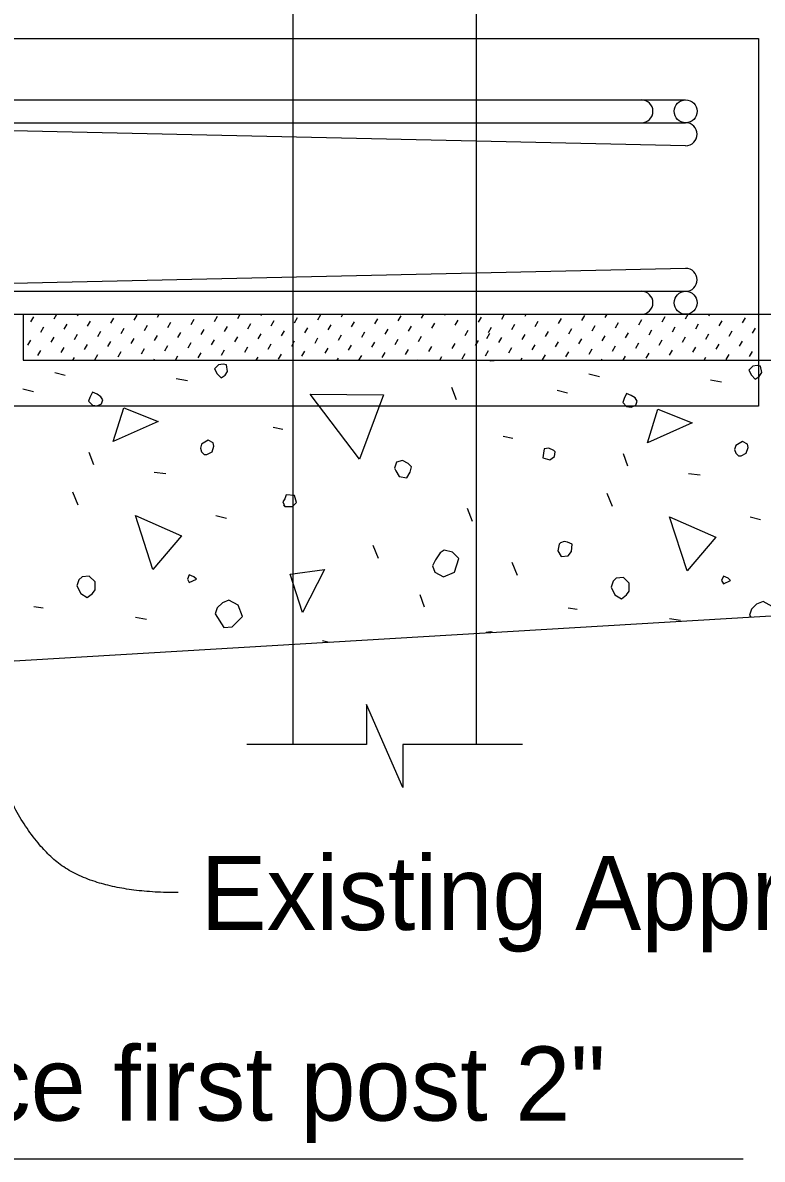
# Model space of a CAD drawing. Extents: x 1 to 39.2, y 0 to 26.
# Drawn here: x 7.686 to 9.698, y 8.522 to 11.612 of the extents above; entities that cross this region are included whole.
import ezdxf

# ---------------------------------------------------------------- set-up
doc = ezdxf.new("R2010")
doc.units = 0
for name, color, linetype in [('Dimension', 7, 'Continuous'), ('Miscellaneous', 7, 'Continuous'), ('Rebar', 7, 'Continuous'), ('TextStructures', 7, 'Continuous'), ('TrafBarrierConc', 7, 'Continuous')]:
    doc.layers.add(name, color=color, linetype=linetype)

msp = doc.modelspace()

# ---------------------------------------------------------------- linework, layer by layer
at = {"layer": 'Dimension'}
msp.add_line((9.6459, 8.5219), (6.3055, 8.5219), dxfattribs=at)
msp.add_lwpolyline([(9.0455, 9.6494), (8.7202, 9.6494), (8.7202, 9.5332), (8.6208, 9.7582), (8.6208, 9.6494), (8.2955, 9.6494)], dxfattribs=at)
msp.add_open_spline([(8.1083, 9.2469), (7.8622, 9.2469), (7.6571, 9.4476), (7.5614, 9.7898), (7.5876, 10.3007)], degree=2, dxfattribs=at)
at = {"layer": 'Miscellaneous'}
for p, q in [((7.771, 10.8069), (7.7784, 10.8196)), ((7.8345, 10.815), (7.8372, 10.8196)), ((7.9892, 10.8035), (7.9973, 10.8175)), ((8.0527, 10.8116), (8.0573, 10.8196)), ((8.2708, 10.8082), (8.2775, 10.8196)), ((8.3343, 10.8163), (8.3363, 10.8196)), ((8.489, 10.8048), (8.4971, 10.8188)), ((8.5525, 10.8129), (8.5564, 10.8196)), ((8.7707, 10.8095), (8.7765, 10.8196)), ((8.8342, 10.8176), (8.8353, 10.8196)), ((8.9888, 10.8061), (8.9967, 10.8196)), ((9.0523, 10.8142), (9.0555, 10.8196)), ((9.2705, 10.8108), (9.2756, 10.8196)), ((9.334, 10.8189), (9.3344, 10.8196)), ((9.4887, 10.8075), (9.4957, 10.8196)), ((9.5522, 10.8156), (9.5545, 10.8196)), ((7.7075, 10.7988), (7.7156, 10.8128)), ((7.7987, 10.7792), (7.8068, 10.7932)), ((7.8622, 10.7873), (7.8703, 10.8013)), ((7.9257, 10.7954), (7.9338, 10.8094)), ((8.0169, 10.7758), (8.025, 10.7898)), ((8.0804, 10.7839), (8.0885, 10.7979)), ((8.1438, 10.792), (8.1519, 10.806)), ((8.2073, 10.8001), (8.2154, 10.8141)), ((8.235, 10.7724), (8.2431, 10.7864)), ((8.2985, 10.7805), (8.3066, 10.7945)), ((8.362, 10.7886), (8.3701, 10.8026)), ((8.4255, 10.7967), (8.4336, 10.8107)), ((8.5167, 10.7771), (8.5248, 10.7911)), ((8.5802, 10.7852), (8.5883, 10.7992)), ((8.6437, 10.7933), (8.6518, 10.8073)), ((8.7072, 10.8014), (8.7153, 10.8154)), ((8.7349, 10.7737), (8.743, 10.7877)), ((8.7984, 10.7818), (8.8065, 10.7958)), ((8.8619, 10.7899), (8.87, 10.8039)), ((8.9253, 10.798), (8.9334, 10.812)), ((9.0165, 10.7784), (9.0246, 10.7924)), ((9.08, 10.7865), (9.0881, 10.8005)), ((9.1435, 10.7946), (9.1516, 10.8086)), ((9.207, 10.8027), (9.2151, 10.8167)), ((9.2347, 10.775), (9.2428, 10.789)), ((9.2982, 10.7832), (9.3063, 10.7971)), ((9.3617, 10.7913), (9.3698, 10.8052)), ((9.4252, 10.7994), (9.4333, 10.8134)), ((9.5164, 10.7798), (9.5245, 10.7938)), ((9.5799, 10.7879), (9.588, 10.8019)), ((9.6434, 10.796), (9.6515, 10.81)), ((7.7352, 10.7711), (7.7433, 10.7851)), ((7.7629, 10.7434), (7.771, 10.7574)), ((7.8264, 10.7515), (7.8345, 10.7655)), ((7.8899, 10.7596), (7.898, 10.7736)), ((7.9534, 10.7677), (7.9615, 10.7817)), ((8.0446, 10.7481), (8.0527, 10.7621)), ((8.108, 10.7562), (8.1161, 10.7702)), ((8.1715, 10.7643), (8.1796, 10.7783)), ((8.2627, 10.7447), (8.2708, 10.7587)), ((8.3262, 10.7528), (8.3343, 10.7668)), ((8.3897, 10.7609), (8.3978, 10.7749)), ((8.4532, 10.769), (8.4613, 10.783)), ((8.4809, 10.7413), (8.489, 10.7553)), ((8.5444, 10.7494), (8.5525, 10.7634)), ((8.6079, 10.7575), (8.616, 10.7715)), ((8.6714, 10.7656), (8.6795, 10.7796)), ((8.7626, 10.746), (8.7707, 10.76)), ((8.8895, 10.7622), (8.8976, 10.7762)), ((8.9485, 10.7541), (8.9566, 10.7681)), ((8.953, 10.7703), (8.9611, 10.7843)), ((8.9807, 10.7426), (8.9888, 10.7566)), ((9.0442, 10.7507), (9.0523, 10.7647)), ((9.1077, 10.7588), (9.1158, 10.7728)), ((9.1712, 10.7669), (9.1793, 10.7809)), ((9.2624, 10.7474), (9.2705, 10.7613)), ((9.3259, 10.7555), (9.334, 10.7695)), ((9.3894, 10.7636), (9.3975, 10.7776)), ((9.4529, 10.7717), (9.461, 10.7857)), ((9.4806, 10.744), (9.4887, 10.758)), ((9.5441, 10.7521), (9.5522, 10.7661)), ((9.6076, 10.7602), (9.6157, 10.7742)), ((9.671, 10.7683), (9.6792, 10.7823)), ((7.6994, 10.7353), (7.7075, 10.7493)), ((7.7906, 10.7157), (7.7987, 10.7297)), ((7.8541, 10.7238), (7.8622, 10.7378)), ((7.9176, 10.7319), (7.9257, 10.7459)), ((7.9811, 10.74), (7.9892, 10.754)), ((8.0088, 10.7123), (8.0169, 10.7263)), ((8.0723, 10.7204), (8.0804, 10.7344)), ((8.1357, 10.7285), (8.1438, 10.7425)), ((8.1992, 10.7366), (8.2073, 10.7506)), ((8.2904, 10.717), (8.2985, 10.731)), ((8.3539, 10.7251), (8.362, 10.7391)), ((8.4174, 10.7332), (8.4255, 10.7472)), ((8.5086, 10.7136), (8.5167, 10.7276)), ((8.5721, 10.7217), (8.5802, 10.7357)), ((8.6356, 10.7298), (8.6437, 10.7438)), ((8.6991, 10.7379), (8.7072, 10.7519)), ((8.7903, 10.7183), (8.7984, 10.7323)), ((8.8538, 10.7264), (8.8619, 10.7404)), ((8.9172, 10.7345), (8.9253, 10.7485)), ((9.0084, 10.7149), (9.0165, 10.7289)), ((9.0719, 10.723), (9.08, 10.737)), ((9.1354, 10.7311), (9.1435, 10.7451)), ((9.1989, 10.7393), (9.207, 10.7532)), ((9.2266, 10.7116), (9.2347, 10.7256)), ((9.2901, 10.7197), (9.2982, 10.7337)), ((9.3536, 10.7278), (9.3617, 10.7418)), ((9.4171, 10.7359), (9.4252, 10.7499)), ((9.5083, 10.7163), (9.5164, 10.7303)), ((9.5718, 10.7244), (9.5799, 10.7384)), ((9.6353, 10.7325), (9.6434, 10.7465)), ((7.7271, 10.7076), (7.7352, 10.7216)), ((7.8221, 10.6946), (7.8264, 10.702)), ((7.8818, 10.6961), (7.8899, 10.7101)), ((7.9453, 10.7042), (7.9534, 10.7182)), ((8.0423, 10.6946), (8.0446, 10.6986)), ((8.1011, 10.6946), (8.108, 10.7067)), ((8.1634, 10.7008), (8.1715, 10.7148)), ((8.2269, 10.7089), (8.235, 10.7229)), ((8.2624, 10.6946), (8.2627, 10.6952)), ((8.3212, 10.6946), (8.3262, 10.7033)), ((8.3816, 10.6974), (8.3897, 10.7114)), ((8.4451, 10.7055), (8.4532, 10.7195)), ((8.5413, 10.6946), (8.5444, 10.6999)), ((8.6001, 10.6946), (8.6079, 10.708)), ((8.6633, 10.7021), (8.6714, 10.7161)), ((8.7268, 10.7102), (8.7349, 10.7242)), ((8.7615, 10.6946), (8.7626, 10.6965)), ((8.8203, 10.6946), (8.8261, 10.7046)), ((8.8814, 10.6987), (8.8895, 10.7127)), ((8.9449, 10.7068), (8.953, 10.7208)), ((9.0404, 10.6946), (9.0442, 10.7012)), ((9.0996, 10.6954), (9.1077, 10.7093)), ((9.1631, 10.7035), (9.1712, 10.7174)), ((9.2605, 10.6946), (9.2624, 10.6979)), ((9.3193, 10.6946), (9.3259, 10.706)), ((9.3813, 10.7001), (9.3894, 10.7141)), ((9.4448, 10.7082), (9.4529, 10.7222)), ((9.5395, 10.6946), (9.5441, 10.7026)), ((9.5995, 10.6967), (9.6076, 10.7107)), ((9.6629, 10.7048), (9.671, 10.7188)), ((7.773, 10.661), (7.8013, 10.6539)), ((8.1036, 10.6451), (8.1336, 10.6398)), ((9.2261, 10.6575), (9.2544, 10.6504)), ((9.5567, 10.6416), (9.5867, 10.6363)), ((7.6864, 10.6168), (7.7147, 10.6097)), ((8.8655, 10.5868), (8.8531, 10.6204)), ((9.1395, 10.6133), (9.1678, 10.6062)), ((8.367, 10.5125), (8.3935, 10.5072)), ((8.9927, 10.4878), (9.0193, 10.4825)), ((7.8791, 10.41), (7.8667, 10.4436)), ((9.3322, 10.4065), (9.3198, 10.44)), ((8.0435, 10.3905), (8.0753, 10.387)), ((9.4966, 10.387), (9.5284, 10.3835)), ((7.8366, 10.3004), (7.8225, 10.3357)), ((9.2897, 10.2969), (9.2756, 10.3322)), ((8.2114, 10.2721), (8.2397, 10.265)), ((8.9097, 10.2562), (8.8955, 10.2915)), ((9.6645, 10.2686), (9.6928, 10.2615)), ((8.6533, 10.1554), (8.6392, 10.1908)), ((9.0316, 10.1095), (9.0175, 10.1448)), ((8.7789, 10.0228), (8.7665, 10.0564)), ((7.7164, 10.0246), (7.7412, 10.0211)), ((9.1695, 10.0211), (9.1943, 10.0175)), ((7.9922, 9.9963), (8.0222, 9.991)), ((9.4453, 9.9928), (9.4754, 9.9875)), ((8.5013, 9.9327), (8.5195, 9.9281))]:
    msp.add_line(p, q, dxfattribs=at)
for points in [[(8.9204, 9.6494), (8.9204, 13.4695), (8.4204, 13.4695), (8.4204, 9.6494)], [(8.9563, 10.6946), (8.9574, 10.6928), (8.9804, 10.6946), (8.9804, 10.6946)], [(8.2149, 10.6575), (8.2255, 10.6469), (8.2361, 10.6539), (8.2432, 10.6645), (8.2397, 10.6822), (8.2308, 10.684), (8.2185, 10.6822), (8.2079, 10.6716), (8.2149, 10.6575)], [(9.668, 10.6539), (9.6786, 10.6433), (9.6892, 10.6504), (9.6963, 10.661), (9.6928, 10.6787), (9.6839, 10.6805), (9.6716, 10.6787), (9.661, 10.6681), (9.668, 10.6539)], [(7.8755, 10.5726), (7.8879, 10.5709), (7.9003, 10.5762), (7.9038, 10.5868), (7.8985, 10.5956), (7.8879, 10.6027), (7.8755, 10.608), (7.8685, 10.5938), (7.8649, 10.5832), (7.8755, 10.5726)], [(8.6021, 10.4259), (8.4677, 10.6027), (8.6675, 10.6009), (8.6021, 10.4259)], [(9.3286, 10.5691), (9.341, 10.5673), (9.3534, 10.5726), (9.3569, 10.5832), (9.3516, 10.5921), (9.341, 10.5991), (9.3286, 10.6044), (9.3216, 10.5903), (9.318, 10.5797), (9.3286, 10.5691)], [(7.9321, 10.4736), (7.9604, 10.5656), (8.0541, 10.5284), (7.9321, 10.4736)], [(9.3852, 10.4701), (9.4135, 10.562), (9.5072, 10.5249), (9.3852, 10.4701)], [(8.1796, 10.4383), (8.1866, 10.4383), (8.2008, 10.4453), (8.2061, 10.4613), (8.2043, 10.4701), (8.1902, 10.4772), (8.1725, 10.4666), (8.169, 10.4559), (8.1725, 10.4453), (8.1796, 10.4383)], [(9.1006, 10.4294), (9.12, 10.4241), (9.1324, 10.433), (9.1342, 10.4453), (9.1306, 10.4489), (9.1165, 10.4559), (9.1041, 10.4542), (9.1024, 10.4418), (9.1006, 10.4294)], [(9.6327, 10.4347), (9.6398, 10.4347), (9.6539, 10.4418), (9.6592, 10.4577), (9.6574, 10.4666), (9.6433, 10.4736), (9.6256, 10.463), (9.6221, 10.4524), (9.6256, 10.4418), (9.6327, 10.4347)], [(8.7011, 10.3941), (8.7099, 10.3782), (8.7311, 10.3746), (8.74, 10.3905), (8.7435, 10.4047), (8.7347, 10.4135), (8.7187, 10.4224), (8.7028, 10.4171), (8.6975, 10.4011), (8.7011, 10.3941)], [(8.3988, 10.2969), (8.42, 10.2969), (8.4306, 10.3075), (8.4253, 10.3269), (8.4023, 10.3287), (8.3988, 10.3181), (8.3935, 10.3092), (8.3988, 10.2969), (8.3952, 10.3004)], [(8.0399, 10.1254), (7.9922, 10.2721), (8.1177, 10.2173), (8.0399, 10.1254)], [(9.493, 10.1218), (9.4453, 10.2686), (9.5708, 10.2138), (9.493, 10.1218)], [(9.1412, 10.1766), (9.1501, 10.1607), (9.1695, 10.1625), (9.1784, 10.1749), (9.1801, 10.1943), (9.1678, 10.1996), (9.1589, 10.2014), (9.1483, 10.1979), (9.1448, 10.1943), (9.1412, 10.1766)], [(8.8071, 10.1183), (8.8301, 10.1059), (8.8602, 10.1183), (8.8725, 10.1554), (8.8549, 10.1731), (8.8319, 10.1784), (8.8213, 10.1713), (8.8089, 10.1519), (8.8001, 10.136), (8.8071, 10.1183)], [(7.8331, 10.0812), (7.8437, 10.06), (7.8614, 10.0494), (7.8755, 10.06), (7.8826, 10.0706), (7.8826, 10.0918), (7.8667, 10.1077), (7.8472, 10.1059), (7.8384, 10.0971), (7.8331, 10.0812)], [(8.1389, 10.09), (8.1584, 10.0989), (8.1513, 10.1059), (8.1389, 10.1112), (8.1336, 10.0989), (8.1389, 10.09)], [(8.4465, 10.0087), (8.4129, 10.113), (8.5066, 10.1254), (8.4465, 10.0087)], [(9.592, 10.0865), (9.6115, 10.0953), (9.6044, 10.1024), (9.592, 10.1077), (9.5867, 10.0953), (9.592, 10.0865)], [(9.2862, 10.0776), (9.2968, 10.0564), (9.3145, 10.0458), (9.3286, 10.0564), (9.3357, 10.067), (9.3357, 10.0883), (9.3198, 10.1042), (9.3003, 10.1024), (9.2915, 10.0936), (9.2862, 10.0776)], [(8.2096, 10.0052), (8.2326, 9.968), (8.2556, 9.9698), (8.2644, 9.9787), (8.2839, 9.9981), (8.2715, 10.0282), (8.2468, 10.0423), (8.2291, 10.0352), (8.2149, 10.0211), (8.2096, 10.0052)], [(9.7347, 10.0001), (9.7246, 10.0246), (9.6999, 10.0388), (9.6822, 10.0317), (9.668, 10.0175), (9.6627, 10.0016)], [(9.6627, 10.0016), (9.6662, 9.9961)], [(8.9649, 9.9545), (8.9592, 9.9557), (8.9468, 9.9539), (8.9463, 9.9534)]]:
    msp.add_lwpolyline(points, dxfattribs=at)
at = {"layer": 'Rebar'}
for p, q in [((5.8537, 11.403), (9.4891, 11.403)), ((5.8537, 11.3405), (9.4891, 11.3405)), ((9.4891, 11.2781), (6.687, 11.3405)), ((9.4891, 10.9445), (6.687, 10.8821)), ((5.8537, 10.8821), (9.4891, 10.8821)), ((5.8537, 10.8196), (9.4891, 10.8196))]:
    msp.add_line(p, q, dxfattribs=at)
for centre in [(9.4891, 11.3717), (9.4891, 10.8509)]:
    msp.add_circle(centre, 0.0312, dxfattribs=at)
for centre in [(9.3689, 11.3717), (9.4891, 11.3093), (9.4891, 11.3093), (9.4891, 10.9133), (9.3689, 10.8509)]:
    msp.add_arc(centre, 0.0312, 270, 90, dxfattribs=at)
at = {"layer": 'TrafBarrierConc'}
for p, q in [((6.687, 11.5696), (9.687, 11.5696)), ((9.687, 11.5696), (9.687, 10.8196)), ((5.687, 10.8196), (11.4105, 10.8196)), ((7.6871, 10.8196), (7.6871, 10.6946)), ((7.6871, 10.6946), (11.4105, 10.6946)), ((6.687, 9.8196), (10.907, 10.0696))]:
    msp.add_line(p, q, dxfattribs=at)
msp.add_lwpolyline([(9.687, 10.8196), (9.687, 10.5696), (6.687, 10.5696), (6.687, 10.8196)], dxfattribs=at)

# ---------------------------------------------------------------- texts
at = {"layer": 'TextStructures'}
for s, p in [('Existing Approach Slab', (8.1696, 9.1453)), ('Place first post 2"', (7.1828, 8.627))]:
    msp.add_text(s, height=0.2016, dxfattribs=at).set_placement(p)

doc.saveas('drawing.dxf')
